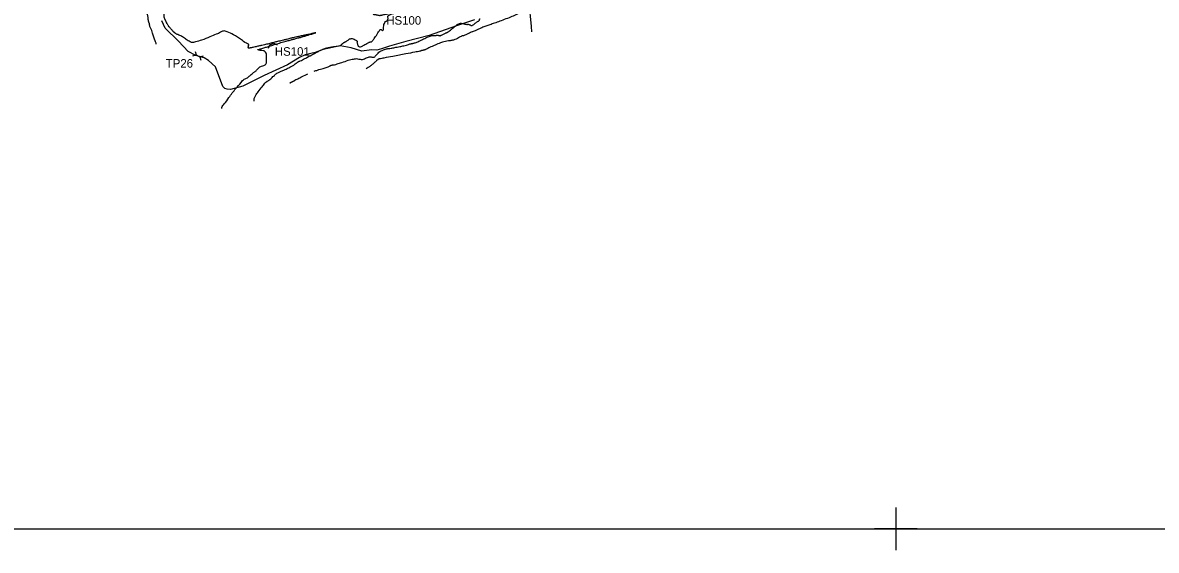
# Model space of a CAD drawing. Extents: x -478645 to -472650, y -1118147 to -1113892.
# Drawn here: x -475798 to -474470, y -1118147 to -1117529 of the extents above; entities that cross this region are included whole.
import ezdxf

# ---------------------------------------------------------------- set-up
doc = ezdxf.new("R2010")
doc.units = 0
for name, color, linetype in [('hospodářské sjezdy', 7, 'Continuous'), ('Implicitní', 7, 'Continuous'), ('ObPÚ', 7, 'Continuous'), ('TP_stavajicí_mosty', 7, 'Continuous'), ('VAK_vodovod', 7, 'Continuous'), ('Vrstevnice_hlavni', 7, 'Continuous'), ('Vrstevnice_vedlejsi', 7, 'Continuous'), ('Z_razitko', 7, 'Continuous')]:
    doc.layers.add(name, color=color, linetype=linetype)

msp = doc.modelspace()

# ---------------------------------------------------------------- linework, layer by layer
at = {"layer": 'hospodářské sjezdy'}
for p, q in [((-475510.362, -1117558.337), (-475508.621, -1117554.442)), ((-475508.621, -1117554.442), (-475504.059, -1117552.695)), ((-475504.059, -1117552.695), (-475500.163, -1117554.431))]:
    msp.add_line(p, q, dxfattribs=at)
at = {"layer": 'Implicitní'}
for p, q in [((-474775.405, -1118096.842), (-474775.405, -1118146.842)), ((-474775.405, -1118096.842), (-474775.405, -1118146.842)), ((-474775.405, -1118096.842), (-474775.405, -1118146.842)), ((-474775.405, -1118096.842), (-474775.405, -1118146.842)), ((-474775.405, -1118096.842), (-474775.405, -1118146.842)), ((-474775.405, -1118096.842), (-474775.405, -1118146.842)), ((-474775.405, -1118096.842), (-474775.405, -1118146.842)), ((-474775.405, -1118096.842), (-474775.405, -1118146.842)), ((-474775.405, -1118096.842), (-474775.405, -1118146.842)), ((-474775.405, -1118096.842), (-474775.405, -1118146.842)), ((-474775.405, -1118096.842), (-474775.405, -1118146.842)), ((-474775.405, -1118096.842), (-474775.405, -1118146.842)), ((-474775.405, -1118096.842), (-474775.405, -1118146.842)), ((-474775.405, -1118096.842), (-474775.405, -1118146.842)), ((-474775.405, -1118096.842), (-474775.405, -1118146.842)), ((-474775.405, -1118096.842), (-474775.405, -1118146.842)), ((-474775.405, -1118096.842), (-474775.405, -1118146.842)), ((-474750.405, -1118121.842), (-474800.405, -1118121.842)), ((-474750.405, -1118121.842), (-474800.405, -1118121.842)), ((-474750.405, -1118121.842), (-474800.405, -1118121.842)), ((-474750.405, -1118121.842), (-474800.405, -1118121.842)), ((-474750.405, -1118121.842), (-474800.405, -1118121.842)), ((-474750.405, -1118121.842), (-474800.405, -1118121.842)), ((-474750.405, -1118121.842), (-474800.405, -1118121.842)), ((-474750.405, -1118121.842), (-474800.405, -1118121.842)), ((-474750.405, -1118121.842), (-474800.405, -1118121.842)), ((-474750.405, -1118121.842), (-474800.405, -1118121.842)), ((-474750.405, -1118121.842), (-474800.405, -1118121.842)), ((-474750.405, -1118121.842), (-474800.405, -1118121.842)), ((-474750.405, -1118121.842), (-474800.405, -1118121.842)), ((-474750.405, -1118121.842), (-474800.405, -1118121.842)), ((-474750.405, -1118121.842), (-474800.405, -1118121.842)), ((-474750.405, -1118121.842), (-474800.405, -1118121.842)), ((-474750.405, -1118121.842), (-474800.405, -1118121.842))]:
    msp.add_line(p, q, dxfattribs=at)
at = {"layer": 'ObPÚ'}
msp.add_lwpolyline([(-475268.9, -1117525.26), (-475289.93, -1117532.25), (-475322.19, -1117543.71), (-475349.39, -1117550.54), (-475368.41, -1117555.92), (-475377.83, -1117559.32), (-475383.54, -1117560.72), (-475389.46, -1117560.35), (-475400.94, -1117561.75), (-475413.64, -1117557.86), (-475426.29, -1117555.57), (-475446.26, -1117560.07), (-475455.63, -1117563.41), (-475467.2, -1117566.34), (-475474.1, -1117569.26), (-475488.02, -1117577.89), (-475515.48, -1117590.46), (-475540.51, -1117602.84), (-475554.82, -1117606.85), (-475558.86, -1117606.62), (-475561.43, -1117605.62), (-475563.77, -1117603.33), (-475572.22, -1117580.45), (-475580.66, -1117572.89), (-475585.86, -1117569.9), (-475595.57, -1117567.11), (-475604.45, -1117562.28), (-475615.81, -1117550), (-475631.28, -1117534.84), (-475635.27, -1117526.54)], dxfattribs=at)
at = {"layer": 'TP_stavajicí_mosty'}
for p, q in [((-475599.092, -1117567.516), (-475595.023, -1117566.237)), ((-475596.258, -1117562.128), (-475595.007, -1117566.206)), ((-475595.023, -1117566.237), (-475590.691, -1117568.494)), ((-475595.007, -1117566.206), (-475590.694, -1117568.499)), ((-475590.694, -1117568.499), (-475586.614, -1117567.253)), ((-475590.691, -1117568.494), (-475589.407, -1117572.561))]:
    msp.add_line(p, q, dxfattribs=at)
at = {"layer": 'VAK_vodovod'}
msp.add_lwpolyline([(-475206.31, -1117500.21), (-475205.35, -1117504.74), (-475202.43, -1117532.88), (-475202.196, -1117539.099)], dxfattribs=at)
at = {"layer": 'Vrstevnice_hlavni'}
for points in [[(-475302.129, -1117540.418), (-475301.757, -1117540.328), (-475301.222, -1117540.101), (-475300.524, -1117539.737), (-475299.664, -1117539.236), (-475298.24, -1117538.184), (-475296.249, -1117536.581), (-475293.694, -1117534.427), (-475291.679, -1117532.752), (-475290.205, -1117531.556), (-475289.272, -1117530.84), (-475288.579, -1117530.363), (-475288.127, -1117530.126), (-475287.915, -1117530.128), (-475287.482, -1117529.999), (-475286.828, -1117529.737), (-475285.954, -1117529.344), (-475284.598, -1117529.278), (-475282.76, -1117529.538), (-475280.44, -1117530.124), (-475278.649, -1117530.467), (-475277.386, -1117530.566), (-475276.651, -1117530.422), (-475275.765, -1117530.525), (-475274.728, -1117530.874), (-475273.54, -1117531.469), (-475272.677, -1117531.849), (-475272.138, -1117532.012), (-475271.923, -1117531.959), (-475271.179, -1117531.475), (-475269.906, -1117530.56), (-475268.104, -1117529.214), (-475266.557, -1117528.111), (-475265.266, -1117527.253), (-475264.231, -1117526.639), (-475263.541, -1117526.073), (-475263.195, -1117525.553), (-475263.193, -1117525.081), (-475263.1, -1117524.687), (-475262.916, -1117524.369), (-475262.366, -1117523.89)], [(-475456.866, -1117585.486), (-475452.783, -1117584.035), (-475446.356, -1117582.048), (-475441.745, -1117580.551), (-475438.951, -1117579.545), (-475437.974, -1117579.029), (-475437.298, -1117578.679), (-475436.923, -1117578.493), (-475436.85, -1117578.472), (-475436.748, -1117578.445), (-475436.618, -1117578.411), (-475436.458, -1117578.372), (-475436.094, -1117578.291), (-475435.525, -1117578.169), (-475434.752, -1117578.006), (-475434.037, -1117577.894), (-475433.381, -1117577.833), (-475432.784, -1117577.824), (-475429.821, -1117576.949), (-475424.491, -1117575.209), (-475416.794, -1117572.603), (-475410.659, -1117571.111), (-475406.087, -1117570.735), (-475403.076, -1117571.472), (-475400.312, -1117571.538), (-475397.793, -1117570.931), (-475395.521, -1117569.651), (-475393.326, -1117568.87), (-475391.209, -1117568.588), (-475389.171, -1117568.805), (-475387.676, -1117568.907), (-475386.726, -1117568.894), (-475386.318, -1117568.767), (-475385.396, -1117567.934), (-475383.957, -1117566.397), (-475382.002, -1117564.155), (-475379.743, -1117562.346), (-475377.178, -1117560.971), (-475374.308, -1117560.029), (-475372.059, -1117559.365), (-475370.431, -1117558.98), (-475369.423, -1117558.872), (-475366.774, -1117558.428), (-475362.484, -1117557.646), (-475356.552, -1117556.528), (-475351.893, -1117555.551), (-475348.507, -1117554.716), (-475346.394, -1117554.022), (-475344.608, -1117553.495), (-475343.149, -1117553.134), (-475342.018, -1117552.938), (-475340.689, -1117552.646), (-475339.164, -1117552.256), (-475337.441, -1117551.77), (-475335.328, -1117550.943), (-475332.824, -1117549.775), (-475329.928, -1117548.268), (-475327.185, -1117546.894), (-475324.593, -1117545.656), (-475322.153, -1117544.552), (-475319.871, -1117543.816), (-475317.748, -1117543.447), (-475315.784, -1117543.445), (-475314.344, -1117543.395), (-475313.428, -1117543.297), (-475313.036, -1117543.153), (-475312.41, -1117543.144), (-475311.552, -1117543.271), (-475310.461, -1117543.534), (-475309.687, -1117543.694), (-475309.23, -1117543.752), (-475309.09, -1117543.707), (-475308.905, -1117543.628), (-475308.675, -1117543.515), (-475308.399, -1117543.367), (-475307.591, -1117542.967), (-475306.25, -1117542.315), (-475304.376, -1117541.412), (-475303.003, -1117540.779), (-475302.129, -1117540.418)], [(-475485.049, -1117599.346), (-475484.814, -1117599.131), (-475484.636, -1117598.968), (-475484.398, -1117598.748), (-475484.099, -1117598.472), (-475483.783, -1117598.241), (-475483.448, -1117598.055), (-475483.095, -1117597.914), (-475482.573, -1117597.685), (-475481.88, -1117597.37), (-475481.018, -1117596.966), (-475480.311, -1117596.594), (-475479.758, -1117596.252), (-475479.36, -1117595.941), (-475476.899, -1117594.666), (-475472.378, -1117592.427), (-475465.794, -1117589.225), (-475464.358, -1117588.559)]]:
    msp.add_spline(points, degree=3, dxfattribs=at)
at = {"layer": 'Vrstevnice_vedlejsi'}
for points in [[(-475641.77, -1117553.631), (-475643.068, -1117549.962), (-475646.308, -1117540.742), (-475648.452, -1117534.546), (-475649.5, -1117531.375), (-475649.451, -1117531.228), (-475649.464, -1117531.075), (-475649.538, -1117530.916), (-475649.672, -1117530.75), (-475649.761, -1117530.577), (-475649.803, -1117530.397), (-475649.8, -1117530.209), (-475649.809, -1117529.999), (-475649.832, -1117529.768), (-475649.868, -1117529.516), (-475649.919, -1117529.275), (-475649.983, -1117529.045), (-475650.063, -1117528.827), (-475650.168, -1117528.586), (-475650.299, -1117528.323), (-475650.457, -1117528.038), (-475650.586, -1117527.752), (-475650.687, -1117527.464), (-475650.758, -1117527.176), (-475650.821, -1117526.851), (-475650.874, -1117526.491), (-475650.917, -1117526.094), (-475650.978, -1117525.719), (-475651.055, -1117525.365), (-475651.148, -1117525.031), (-475651.227, -1117524.703), (-475651.29, -1117524.379), (-475651.339, -1117524.06), (-475651.391, -1117523.447), (-475651.446, -1117522.54), (-475651.504, -1117521.34), (-475652.885, -1117517.284), (-475655.59, -1117510.374), (-475659.617, -1117500.609), (-475662.566, -1117493.686), (-475664.435, -1117489.605), (-475665.225, -1117488.367), (-475665.905, -1117487.354), (-475666.475, -1117486.568)], [(-475505.295, -1117551.98), (-475507.551, -1117552.591), (-475509.948, -1117553.215), (-475512.486, -1117553.85), (-475515.163, -1117554.497), (-475518.292, -1117555.216), (-475521.871, -1117556.006), (-475525.902, -1117556.867), (-475528.724, -1117557.471), (-475530.338, -1117557.817), (-475530.744, -1117557.905), (-475531.366, -1117558.045), (-475532.204, -1117558.236), (-475533.257, -1117558.479), (-475533.868, -1117558.386), (-475534.036, -1117557.958), (-475533.762, -1117557.195), (-475533.668, -1117556.62), (-475533.754, -1117556.231), (-475534.02, -1117556.03), (-475534.036, -1117555.74), (-475533.803, -1117555.361), (-475533.319, -1117554.892), (-475536.09, -1117552.627), (-475542.114, -1117548.565), (-475551.392, -1117542.705), (-475558.534, -1117539.291), (-475563.537, -1117538.323), (-475566.404, -1117539.802), (-475571.537, -1117542.068), (-475578.936, -1117545.122), (-475588.601, -1117548.964), (-475595.854, -1117551.112), (-475600.695, -1117551.567), (-475603.123, -1117550.329), (-475605.456, -1117548.976), (-475607.695, -1117547.509), (-475609.84, -1117545.927), (-475612, -1117544.573), (-475614.176, -1117543.447), (-475616.369, -1117542.547), (-475617.992, -1117541.827), (-475619.044, -1117541.284), (-475619.527, -1117540.921), (-475619.88, -1117540.654), (-475620.102, -1117540.483), (-475620.195, -1117540.41), (-475620.303, -1117540.316), (-475620.427, -1117540.202), (-475620.567, -1117540.069), (-475620.784, -1117539.876), (-475621.079, -1117539.623), (-475621.452, -1117539.31), (-475622.171, -1117538.56), (-475623.237, -1117537.375), (-475624.649, -1117535.753), (-475625.67, -1117534.6), (-475626.299, -1117533.914), (-475626.536, -1117533.696), (-475626.759, -1117533.473), (-475626.969, -1117533.245), (-475627.164, -1117533.011), (-475627.606, -1117532.278), (-475628.294, -1117531.046), (-475629.229, -1117529.314), (-475629.863, -1117528.14), (-475630.198, -1117527.522), (-475630.233, -1117527.461), (-475630.263, -1117527.404), (-475630.286, -1117527.351), (-475630.304, -1117527.301), (-475630.32, -1117527.241), (-475630.334, -1117527.17), (-475630.346, -1117527.089), (-475630.481, -1117526.786), (-475630.74, -1117526.26), (-475631.122, -1117525.511), (-475631.511, -1117524.711), (-475631.907, -1117523.859), (-475632.309, -1117522.956), (-475632.527, -1117521.891), (-475632.56, -1117520.666), (-475632.41, -1117519.28), (-475632.407, -1117517.897), (-475632.551, -1117516.519), (-475632.844, -1117515.145), (-475633.247, -1117513.606), (-475633.76, -1117511.904), (-475634.383, -1117510.037), (-475635.23, -1117508.166), (-475636.3, -1117506.293), (-475637.593, -1117504.416), (-475638.507, -1117502.998), (-475639.041, -1117502.037), (-475639.195, -1117501.534), (-475639.317, -1117501.146), (-475639.408, -1117500.871)], [(-475390.816, -1117550.995), (-475390.088, -1117551.035), (-475389.214, -1117550.551), (-475388.193, -1117549.545), (-475387.027, -1117548.015), (-475385.616, -1117546.005), (-475383.961, -1117543.516), (-475382.061, -1117540.547), (-475380.678, -1117538.382), (-475379.813, -1117537.022), (-475379.465, -1117536.466), (-475378.865, -1117536.418), (-475378.012, -1117536.879), (-475376.907, -1117537.847), (-475376.092, -1117537.367), (-475375.566, -1117535.439), (-475375.329, -1117532.063), (-475374.554, -1117529.358), (-475373.239, -1117527.323), (-475371.385, -1117525.959), (-475370.342, -1117524.544), (-475370.11, -1117523.077), (-475370.688, -1117521.559), (-475369.775, -1117520.154), (-475367.371, -1117518.862), (-475363.476, -1117517.684), (-475360.575, -1117516.807), (-475358.667, -1117516.232), (-475357.752, -1117515.958), (-475356.778, -1117515.645), (-475355.742, -1117515.292), (-475354.647, -1117514.899), (-475352.934, -1117514.279), (-475350.603, -1117513.432), (-475347.655, -1117512.358), (-475345.746, -1117511.517), (-475344.877, -1117510.908), (-475345.047, -1117510.533), (-475345.49, -1117510.362), (-475346.206, -1117510.397), (-475347.196, -1117510.637), (-475348.3, -1117510.944), (-475349.518, -1117511.318), (-475350.852, -1117511.76), (-475352.296, -1117512.245), (-475353.85, -1117512.772), (-475355.513, -1117513.342), (-475357.083, -1117513.884), (-475358.559, -1117514.397), (-475359.941, -1117514.881), (-475361.329, -1117515.357), (-475362.723, -1117515.826), (-475364.124, -1117516.288), (-475365.566, -1117516.755), (-475367.05, -1117517.228), (-475368.576, -1117517.707), (-475369.889, -1117518.107), (-475370.99, -1117518.428), (-475371.877, -1117518.67), (-475373.133, -1117518.961), (-475374.755, -1117519.302), (-475376.745, -1117519.692), (-475378.098, -1117519.962), (-475378.812, -1117520.111), (-475378.889, -1117520.14), (-475379.051, -1117520.191), (-475379.298, -1117520.266), (-475379.63, -1117520.364), (-475380.458, -1117520.292), (-475381.78, -1117520.049), (-475383.597, -1117519.636), (-475385.069, -1117519.34), (-475386.195, -1117519.162), (-475386.977, -1117519.102), (-475387.419, -1117518.904), (-475387.524, -1117518.569), (-475387.29, -1117518.097), (-475387.096, -1117517.625), (-475386.94, -1117517.153), (-475386.825, -1117516.682), (-475386.067, -1117515.887), (-475384.666, -1117514.768), (-475382.624, -1117513.326), (-475383.427, -1117510.756), (-475387.077, -1117507.059), (-475393.572, -1117502.234), (-475399.575, -1117499.066), (-475405.086, -1117497.552), (-475410.105, -1117497.695), (-475416.214, -1117497.992), (-475423.416, -1117498.444), (-475431.708, -1117499.052), (-475438.838, -1117498.874), (-475444.805, -1117497.912), (-475449.611, -1117496.164), (-475455.657, -1117495.283), (-475462.944, -1117495.27)], [(-475194.832, -1117509.441), (-475197.455, -1117511.503), (-475199.394, -1117513.005), (-475200.647, -1117513.947), (-475201.216, -1117514.329), (-475201.798, -1117514.496), (-475202.394, -1117514.45), (-475203.003, -1117514.189), (-475203.981, -1117513.987), (-475205.327, -1117513.844), (-475207.042, -1117513.76), (-475208.389, -1117513.762), (-475209.368, -1117513.85), (-475209.979, -1117514.024), (-475211.339, -1117514.673), (-475213.448, -1117515.795), (-475216.305, -1117517.391), (-475220.712, -1117519.447), (-475226.667, -1117521.962), (-475234.171, -1117524.936), (-475240.927, -1117527.496), (-475246.935, -1117529.64), (-475252.195, -1117531.369), (-475256.998, -1117533.102), (-475261.346, -1117534.84), (-475265.236, -1117536.582), (-475268.281, -1117537.917), (-475270.479, -1117538.845), (-475271.832, -1117539.367), (-475273.706, -1117540.173), (-475276.101, -1117541.264), (-475279.017, -1117542.64), (-475281.196, -1117543.562), (-475282.638, -1117544.031), (-475283.343, -1117544.047), (-475284.64, -1117544.573), (-475286.529, -1117545.609), (-475289.011, -1117547.155), (-475292.005, -1117548.388), (-475295.511, -1117549.308), (-475299.53, -1117549.914), (-475303.113, -1117550.615), (-475306.259, -1117551.409), (-475308.969, -1117552.298), (-475311.942, -1117553.418), (-475315.176, -1117554.768), (-475318.672, -1117556.349), (-475321.486, -1117557.655), (-475323.617, -1117558.685), (-475325.066, -1117559.439), (-475326.319, -1117560.024), (-475327.376, -1117560.437), (-475328.238, -1117560.681), (-475329.001, -1117560.876), (-475329.666, -1117561.022), (-475330.232, -1117561.12), (-475330.962, -1117561.301), (-475331.856, -1117561.564), (-475332.913, -1117561.911), (-475338.742, -1117563.109), (-475349.34, -1117565.157), (-475364.71, -1117568.055), (-475375.009, -1117569.993), (-475380.238, -1117570.971), (-475380.396, -1117570.988), (-475380.651, -1117571.048), (-475381.004, -1117571.152), (-475381.454, -1117571.3), (-475381.856, -1117571.515), (-475382.21, -1117571.799), (-475382.517, -1117572.151), (-475382.804, -1117572.411), (-475383.072, -1117572.58), (-475383.32, -1117572.658), (-475384.253, -1117573.449), (-475385.871, -1117574.952), (-475388.173, -1117577.168), (-475390.77, -1117579.244), (-475393.662, -1117581.179), (-475395.947, -1117582.498)], [(-475564.919, -1117629.176), (-475564.922, -1117629.133), (-475564.874, -1117627.998), (-475562.118, -1117623.722), (-475556.651, -1117616.307), (-475548.476, -1117605.751), (-475542.468, -1117598.526), (-475538.626, -1117594.634), (-475536.952, -1117594.072), (-475535.05, -1117592.982), (-475532.919, -1117591.364), (-475530.559, -1117589.217), (-475528.633, -1117587.577), (-475527.14, -1117586.444), (-475526.08, -1117585.819), (-475524.903, -1117584.812), (-475523.609, -1117583.423), (-475522.199, -1117581.652), (-475520.436, -1117580.282), (-475518.321, -1117579.313), (-475515.854, -1117578.745), (-475514.086, -1117577.745), (-475513.017, -1117576.315), (-475512.647, -1117574.454), (-475512.491, -1117572.021), (-475512.549, -1117569.018), (-475512.821, -1117565.443), (-475513.815, -1117562.965), (-475515.533, -1117561.582), (-475517.973, -1117561.295), (-475519.914, -1117561.02), (-475521.357, -1117560.759), (-475522.302, -1117560.51), (-475522.723, -1117560.286), (-475522.623, -1117560.086), (-475521.999, -1117559.911), (-475520.854, -1117559.566), (-475519.186, -1117559.052), (-475516.995, -1117558.369), (-475514.79, -1117557.694), (-475512.569, -1117557.029), (-475510.333, -1117556.374), (-475507.843, -1117555.616), (-475505.1, -1117554.757), (-475502.103, -1117553.795), (-475499.019, -1117552.854), (-475495.847, -1117551.933), (-475492.586, -1117551.032), (-475489.661, -1117550.231), (-475487.072, -1117549.528), (-475484.817, -1117548.924), (-475482.93, -1117548.425), (-475481.412, -1117548.032), (-475480.261, -1117547.743), (-475478.33, -1117547.22), (-475475.617, -1117546.461), (-475472.123, -1117545.467), (-475469.59, -1117544.741), (-475468.018, -1117544.283), (-475467.408, -1117544.093), (-475466.804, -1117543.908), (-475466.205, -1117543.726), (-475465.611, -1117543.549), (-475463.768, -1117543.003), (-475460.676, -1117542.089), (-475456.334, -1117540.807), (-475454.837, -1117540.29), (-475456.185, -1117540.54), (-475460.379, -1117541.556), (-475463.389, -1117542.277), (-475465.216, -1117542.702), (-475465.859, -1117542.831), (-475466.637, -1117542.992), (-475467.55, -1117543.185), (-475468.598, -1117543.411), (-475470.526, -1117543.816), (-475473.335, -1117544.401), (-475477.025, -1117545.166), (-475480.042, -1117545.825), (-475482.387, -1117546.381), (-475484.059, -1117546.832), (-475486.334, -1117547.421), (-475489.212, -1117548.148), (-475492.693, -1117549.015), (-475495.776, -1117549.757), (-475498.462, -1117550.377), (-475500.75, -1117550.873), (-475503.028, -1117551.407), (-475505.295, -1117551.98)], [(-475527.054, -1117620.587), (-475527.124, -1117619.711), (-475527.032, -1117617.496), (-475525.458, -1117614.066), (-475522.402, -1117609.422), (-475517.865, -1117603.564), (-475514.53, -1117599.555), (-475512.399, -1117597.394), (-475511.47, -1117597.083), (-475510.229, -1117596.31), (-475508.678, -1117595.076), (-475506.814, -1117593.381), (-475505.07, -1117591.786), (-475503.445, -1117590.292), (-475501.94, -1117588.898), (-475500.342, -1117587.732), (-475498.651, -1117586.792), (-475496.869, -1117586.079), (-475494.231, -1117584.926), (-475490.736, -1117583.331), (-475486.385, -1117581.296), (-475482.813, -1117579.416), (-475480.022, -1117577.691), (-475478.01, -1117576.12), (-475476.482, -1117574.982), (-475475.437, -1117574.277), (-475474.877, -1117574.004), (-475474.322, -1117573.766), (-475473.77, -1117573.563), (-475473.223, -1117573.394), (-475470.385, -1117571.976), (-475465.256, -1117569.309), (-475457.835, -1117565.394), (-475452.445, -1117562.575), (-475449.086, -1117560.853), (-475447.757, -1117560.226), (-475446.671, -1117559.751), (-475445.827, -1117559.427), (-475445.225, -1117559.255), (-475444.804, -1117559.097), (-475444.565, -1117558.955), (-475444.508, -1117558.828), (-475444.341, -1117558.725), (-475444.063, -1117558.645), (-475443.675, -1117558.589), (-475443.078, -1117558.468), (-475442.272, -1117558.281), (-475441.257, -1117558.029), (-475439.879, -1117557.713), (-475438.138, -1117557.333), (-475436.033, -1117556.889), (-475433.701, -1117556.47), (-475431.14, -1117556.077), (-475428.352, -1117555.708), (-475426.504, -1117555.403), (-475425.598, -1117555.161), (-475425.632, -1117554.982), (-475425.479, -1117554.725), (-475425.137, -1117554.392), (-475424.608, -1117553.982), (-475424.031, -1117553.503), (-475423.405, -1117552.957), (-475422.73, -1117552.342), (-475422.163, -1117551.88), (-475421.704, -1117551.57), (-475421.353, -1117551.412), (-475420.857, -1117551.173), (-475420.217, -1117550.852), (-475419.431, -1117550.45), (-475418.338, -1117549.783), (-475416.936, -1117548.851), (-475415.226, -1117547.654), (-475413.303, -1117547.2), (-475411.164, -1117547.489), (-475408.812, -1117548.521), (-475407.272, -1117549.484), (-475406.543, -1117550.379), (-475406.627, -1117551.205), (-475406.41, -1117552.414), (-475405.894, -1117554.006), (-475405.078, -1117555.98), (-475403.583, -1117556.783), (-475401.409, -1117556.415), (-475398.557, -1117554.875), (-475396.194, -1117553.585), (-475394.318, -1117552.543), (-475392.932, -1117551.749), (-475391.764, -1117551.233), (-475390.816, -1117550.995)]]:
    msp.add_spline(points, degree=3, dxfattribs=at)
at = {"layer": 'Z_razitko'}
msp.add_lwpolyline([(-478620.405, -1118121.842), (-472675.405, -1118121.842), (-472675.405, -1113916.842), (-478620.405, -1113916.842)], close=True, dxfattribs=at)

# ---------------------------------------------------------------- texts
at = {"layer": 'hospodářské sjezdy'}
for s, p in [('HS100', (-475372.309, -1117530.836)), ('HS101', (-475502.871, -1117567.273))]:
    msp.add_text(s, height=10, rotation=359.999994, dxfattribs=at).set_placement(p)
at = {"layer": 'TP_stavajicí_mosty'}
msp.add_text('TP26', height=10, rotation=359.999994, dxfattribs=at).set_placement((-475630.66, -1117581.164))

doc.saveas('drawing.dxf')
